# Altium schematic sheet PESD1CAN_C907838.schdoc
size 127 x 101 mm
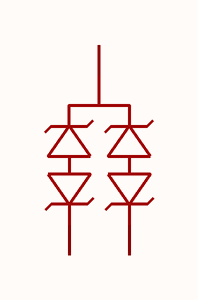
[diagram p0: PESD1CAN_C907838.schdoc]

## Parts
D?  pesd1can_c907838  [SOT-23-3_L2.9-W1.6-P1.90-LS2.8-BR]  (value not drawn)

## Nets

Not connected (* = marked no-connect by the designer): D? 1 2 3

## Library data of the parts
D? = pesd1can_c907838: 极性:双向;反向截止电压(Vrwm):24V;钳位电压:50V;峰值脉冲电流(Ipp):3A@8/20us;峰值脉冲功率(Ppp):150W@8/20us;击穿电压:25V;; Manufacturer: TECH PUBLIC(台舟); AddInBom: yes; ModelId: 89cb27a44ab2466697082bb9fd73a7d0; ModelName: SOT-23-3L_L2.9-W1.6-H1.1-LS2.8-P0.95; ModelTransform: 114.173,110.236,0,90,0,0,0,0,0; Polarity: 双向; Reverse Stand-Off Voltage (Vrwm): 24V; Clamping Voltage: 50V; Voltage - Breakdown: 25V; Reverse Leakage Current (Ir): 80nA; Number of Channels: 双路; level of protection: IEC 61000-4-2；IEC 61000-4-4；IEC 61000-4-5; Type: ESD; Junction Capacitance: 10pF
